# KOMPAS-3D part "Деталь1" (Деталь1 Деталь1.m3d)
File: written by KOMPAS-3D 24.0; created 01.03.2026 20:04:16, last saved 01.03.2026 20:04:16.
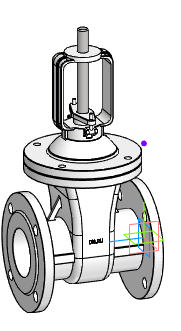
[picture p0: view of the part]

Document properties: Автор: R2D2; Полное имя файла: E:\Работа\Зайцев\GVWR3131M-2W-F-S Задвижка клиновая с выдвижным штоком DN.ru Ду50-200 Ру63\DN80\исходные материалы\Деталь1 Деталь1.m3d

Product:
- Body: Твердое тело1  | qty 1
- Part/product: Деталь1
    additional columns: Типовые

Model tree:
1. Твердое тело1  (labels: Твердое тело1)
2. Точка:1
     Y = 160.5; Координата Y = 160.5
